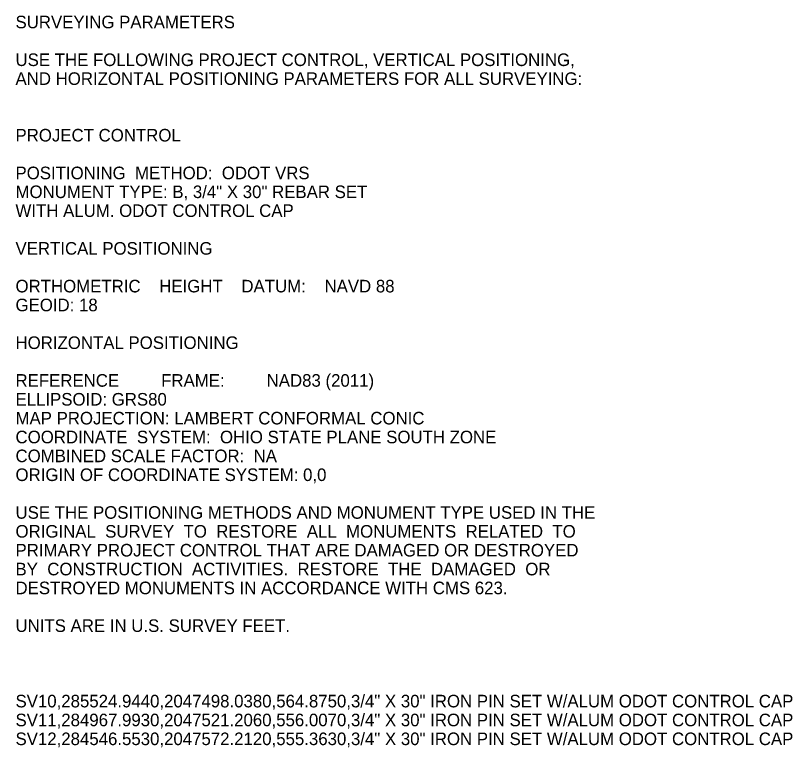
# Model space of a CAD drawing. Extents: x -15.5 to 34, y 0 to 22.
# Drawn here: x -15.55 to -6.89, y 1.5 to 9.65 of the extents above; entities that cross this region are included whole.
import ezdxf

# ---------------------------------------------------------------- set-up
doc = ezdxf.new("R2010")
doc.units = 0
doc.layers.add('SV_X_Text', color=7, linetype='Continuous')

msp = doc.modelspace()

# ---------------------------------------------------------------- texts
at = {"layer": 'SV_X_Text'}
for s, p in [('SURVEYING PARAMETERS', (-15.5494, 9.5091)), ('USE THE FOLLOWING PROJECT CONTROL, VERTICAL POSITIONING,', (-15.5494, 9.0891)), ('AND HORIZONTAL POSITIONING PARAMETERS FOR ALL SURVEYING:', (-15.5494, 8.8791)), ('PROJECT CONTROL', (-15.5494, 8.2491)), ('POSITIONING  METHOD:  ODOT VRS', (-15.5494, 7.8291)), ('MONUMENT TYPE: B, 3/4" X 30" REBAR SET', (-15.5494, 7.6191)), ('WITH ALUM. ODOT CONTROL CAP', (-15.5494, 7.4091)), ('VERTICAL POSITIONING', (-15.5494, 6.9891)), ('ORTHOMETRIC    HEIGHT    DATUM:    NAVD 88', (-15.5494, 6.5691)), ('GEOID: 18', (-15.5494, 6.3591)), ('HORIZONTAL POSITIONING', (-15.5494, 5.9391)), ('REFERENCE         FRAME:         NAD83 (2011)', (-15.5494, 5.5191)), ('ELLIPSOID: GRS80', (-15.5494, 5.3091)), ('MAP PROJECTION: LAMBERT CONFORMAL CONIC', (-15.5494, 5.0991)), ('COORDINATE  SYSTEM:  OHIO STATE PLANE SOUTH ZONE', (-15.5494, 4.8891)), ('COMBINED SCALE FACTOR:  NA', (-15.5494, 4.6791)), ('ORIGIN OF COORDINATE SYSTEM: 0,0', (-15.5494, 4.4691)), ('USE THE POSITIONING METHODS AND MONUMENT TYPE USED IN THE', (-15.5494, 4.0491)), ('ORIGINAL  SURVEY  TO  RESTORE  ALL  MONUMENTS  RELATED  TO', (-15.5494, 3.8391)), ('PRIMARY PROJECT CONTROL THAT ARE DAMAGED OR DESTROYED', (-15.5494, 3.6291)), ('BY  CONSTRUCTION  ACTIVITIES.  RESTORE  THE  DAMAGED  OR', (-15.5494, 3.4191)), ('DESTROYED MONUMENTS IN ACCORDANCE WITH CMS 623.', (-15.5494, 3.2091)), ('UNITS ARE IN U.S. SURVEY FEET.', (-15.5494, 2.7891)), ('SV10,285524.9440,2047498.0380,564.8750,3/4" X 30" IRON PIN SET W/ALUM ODOT CONTROL CAP', (-15.5494, 1.9491)), ('SV11,284967.9930,2047521.2060,556.0070,3/4" X 30" IRON PIN SET W/ALUM ODOT CONTROL CAP', (-15.5494, 1.7391)), ('SV12,284546.5530,2047572.2120,555.3630,3/4" X 30" IRON PIN SET W/ALUM ODOT CONTROL CAP', (-15.5494, 1.5291))]:
    msp.add_text(s, height=0.14, dxfattribs=at).set_placement(p)

doc.saveas('drawing.dxf')
